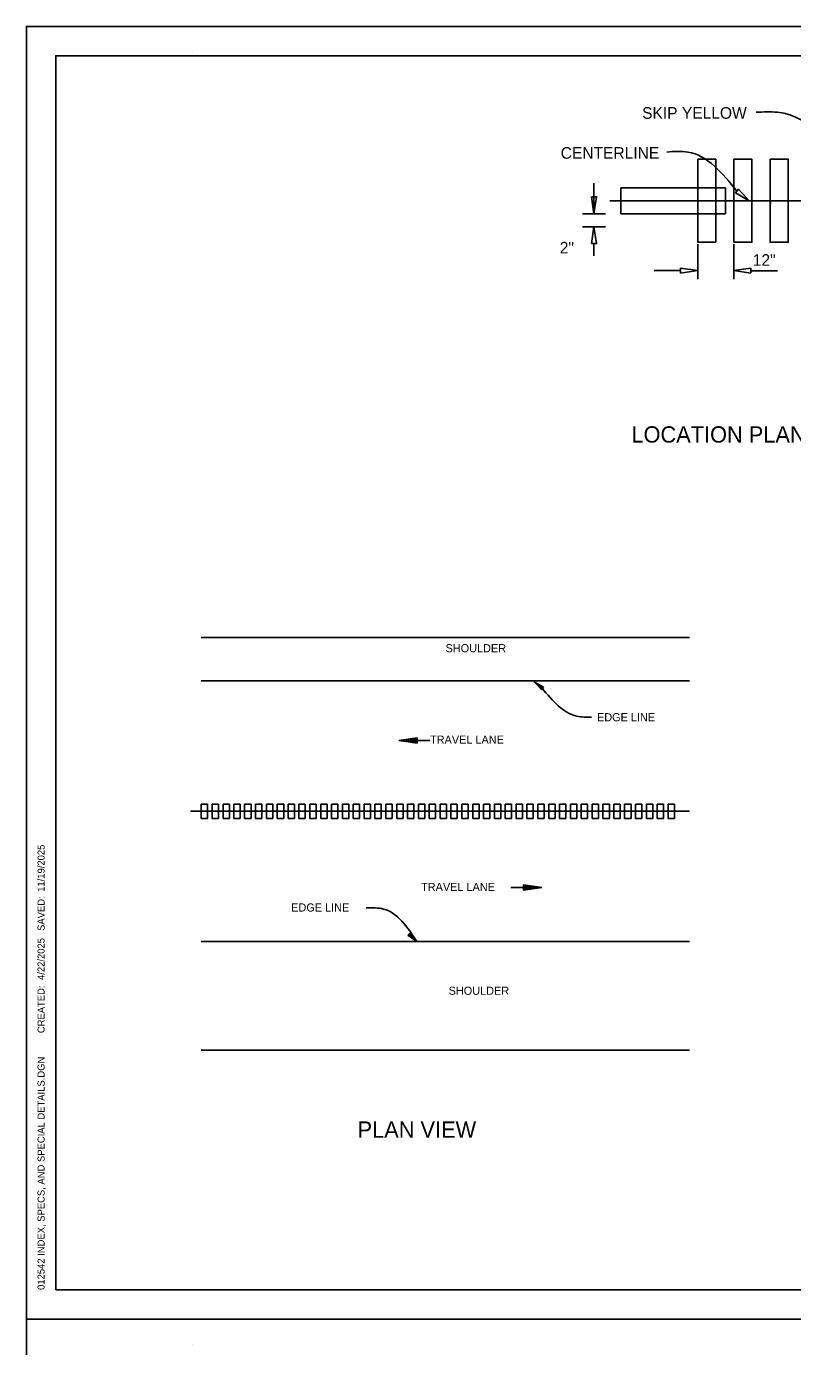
# Model space of a CAD drawing. Extents: x 1371343 to 1376243, y 378740 to 382184.
# Drawn here: x 1371343 to 1371995, y 380917 to 382040 of the extents above; entities that cross this region are included whole.
import ezdxf

# ---------------------------------------------------------------- set-up
doc = ezdxf.new("R2010")
doc.units = 0
for name, color, linetype in [('Default', 7, 'Continuous'), ('SHET_Border-Lines', 7, 'Continuous'), ('SHET_Border-Text', 7, 'Continuous')]:
    doc.layers.add(name, color=color, linetype=linetype)

msp = doc.modelspace()

# ---------------------------------------------------------------- linework, layer by layer
at = {"layer": 'Default'}
for p, q in [((1371826, 381881.1), (1371826, 381907.2)), ((1371849, 381903.2), (1371849, 381881.1)), ((1371849, 381903.2), (1371937.9, 381903.2)), ((1371937.9, 381903.2), (1371937.9, 381881.1)), ((1371839.4, 381892.1), (1372448.3, 381892.1)), ((1371976.3, 381892.1), (1371976.3, 381889.3)), ((1371816.2, 381881.1), (1371835.9, 381881.1)), ((1371849, 381881.1), (1371937.9, 381881.1)), ((1371816.2, 381870.1), (1371835.9, 381870.1)), ((1371826, 381845.4), (1371826, 381855.7)), ((1371914.3, 381825.5), (1371914.3, 381855.1)), ((1371945.1, 381825.4), (1371945.1, 381855.2)), ((1371899.8, 381832.7), (1371877.2, 381832.7)), ((1371982.2, 381832.6), (1371959.5, 381832.6)), ((1371491.8, 381520.5), (1371907.4, 381520.5)), ((1371491.8, 381483.6), (1371698.6, 381483.6)), ((1371907.4, 381483.6), (1371698.6, 381483.6)), ((1371781.5, 381476), (1371775.1, 381482.9)), ((1371783.2, 381478.2), (1371775.1, 381482.9)), ((1371781.6, 381476.2), (1371776.3, 381481.9)), ((1371783.1, 381478), (1371776.3, 381481.9)), ((1371782.9, 381477.8), (1371777.6, 381480.9)), ((1371781.8, 381476.4), (1371777.6, 381480.9)), ((1371781.9, 381476.6), (1371778.8, 381480)), ((1371782.8, 381477.6), (1371778.8, 381480)), ((1371782.6, 381477.4), (1371780, 381479)), ((1371782.1, 381476.7), (1371780, 381479)), ((1371782.5, 381477.3), (1371781.2, 381478)), ((1371782.2, 381476.9), (1371781.2, 381478)), ((1371781.5, 381476), (1371783.2, 381478.2)), ((1371675.5, 381435.2), (1371659.9, 381432.9)), ((1371686.4, 381432.9), (1371659.9, 381432.9)), ((1371675.5, 381430.6), (1371659.9, 381432.9)), ((1371675.5, 381434.8), (1371662.5, 381432.9)), ((1371675.5, 381431), (1371662.5, 381432.9)), ((1371675.5, 381434.5), (1371665.2, 381432.9)), ((1371675.5, 381431.4), (1371665.2, 381432.9)), ((1371675.5, 381434.1), (1371667.7, 381432.9)), ((1371675.5, 381431.7), (1371667.7, 381432.9)), ((1371675.5, 381433.6), (1371670.4, 381432.9)), ((1371675.5, 381432.1), (1371670.4, 381432.9)), ((1371675.5, 381433.3), (1371673, 381432.9)), ((1371675.5, 381432.5), (1371673, 381432.9)), ((1371675.5, 381435.2), (1371675.5, 381430.6)), ((1371497.2, 381378.8), (1371491.8, 381378.8)), ((1371491.8, 381378.8), (1371491.8, 381366.6)), ((1371497.2, 381378.8), (1371497.2, 381366.6)), ((1371506.4, 381378.8), (1371501, 381378.8)), ((1371501, 381378.8), (1371501, 381366.6)), ((1371506.4, 381378.8), (1371506.4, 381366.6)), ((1371515.7, 381378.8), (1371510.3, 381378.8)), ((1371510.3, 381378.8), (1371510.3, 381366.6)), ((1371515.7, 381378.8), (1371515.7, 381366.6)), ((1371524.9, 381378.8), (1371519.5, 381378.8)), ((1371519.5, 381378.8), (1371519.5, 381366.6)), ((1371524.9, 381378.8), (1371524.9, 381366.6)), ((1371534.1, 381378.8), (1371528.7, 381378.8)), ((1371528.7, 381378.8), (1371528.7, 381366.6)), ((1371534.1, 381378.8), (1371534.1, 381366.6)), ((1371543.4, 381378.8), (1371538, 381378.8)), ((1371538, 381378.8), (1371538, 381366.6)), ((1371543.4, 381378.8), (1371543.4, 381366.6)), ((1371552.6, 381378.8), (1371547.2, 381378.8)), ((1371547.2, 381378.8), (1371547.2, 381366.6)), ((1371552.6, 381378.8), (1371552.6, 381366.6)), ((1371561.9, 381378.8), (1371556.5, 381378.8)), ((1371556.5, 381378.8), (1371556.5, 381366.6)), ((1371561.9, 381378.8), (1371561.9, 381366.6)), ((1371571.1, 381378.8), (1371565.7, 381378.8)), ((1371565.7, 381378.8), (1371565.7, 381366.6)), ((1371571.1, 381378.8), (1371571.1, 381366.6)), ((1371580.3, 381378.8), (1371574.9, 381378.8)), ((1371574.9, 381378.8), (1371574.9, 381366.6)), ((1371580.3, 381378.8), (1371580.3, 381366.6)), ((1371589.6, 381378.8), (1371584.2, 381378.8)), ((1371584.2, 381378.8), (1371584.2, 381366.6)), ((1371589.6, 381378.8), (1371589.6, 381366.6)), ((1371598.8, 381378.8), (1371593.4, 381378.8)), ((1371593.4, 381378.8), (1371593.4, 381366.6)), ((1371598.8, 381378.8), (1371598.8, 381366.6)), ((1371608.1, 381378.8), (1371602.7, 381378.8)), ((1371602.7, 381378.8), (1371602.7, 381366.6)), ((1371608.1, 381378.8), (1371608.1, 381366.6)), ((1371617.3, 381378.8), (1371611.9, 381378.8)), ((1371611.9, 381378.8), (1371611.9, 381366.6)), ((1371617.3, 381378.8), (1371617.3, 381366.6)), ((1371626.5, 381378.8), (1371621.1, 381378.8)), ((1371621.1, 381378.8), (1371621.1, 381366.6)), ((1371626.5, 381378.8), (1371626.5, 381366.6)), ((1371635.8, 381378.8), (1371630.4, 381378.8)), ((1371630.4, 381378.8), (1371630.4, 381366.6)), ((1371635.8, 381378.8), (1371635.8, 381366.6)), ((1371645, 381378.8), (1371639.6, 381378.8)), ((1371639.6, 381378.8), (1371639.6, 381366.6)), ((1371645, 381378.8), (1371645, 381366.6)), ((1371654.3, 381378.8), (1371648.9, 381378.8)), ((1371648.9, 381378.8), (1371648.9, 381366.6)), ((1371654.3, 381378.8), (1371654.3, 381366.6)), ((1371663.5, 381378.8), (1371658.1, 381378.8)), ((1371658.1, 381378.8), (1371658.1, 381366.6)), ((1371663.5, 381378.8), (1371663.5, 381366.6)), ((1371672.7, 381378.8), (1371667.3, 381378.8)), ((1371667.3, 381378.8), (1371667.3, 381366.6)), ((1371672.7, 381378.8), (1371672.7, 381366.6)), ((1371682, 381378.8), (1371676.6, 381378.8)), ((1371676.6, 381378.8), (1371676.6, 381366.6)), ((1371682, 381378.8), (1371682, 381366.6)), ((1371691.2, 381378.8), (1371685.8, 381378.8)), ((1371685.8, 381378.8), (1371685.8, 381366.6)), ((1371691.2, 381378.8), (1371691.2, 381366.6)), ((1371700.5, 381378.8), (1371695.1, 381378.8)), ((1371695.1, 381378.8), (1371695.1, 381366.6)), ((1371700.5, 381378.8), (1371700.5, 381366.6)), ((1371709.7, 381378.8), (1371704.3, 381378.8)), ((1371704.3, 381378.8), (1371704.3, 381366.6)), ((1371709.7, 381378.8), (1371709.7, 381366.6)), ((1371719, 381378.8), (1371713.5, 381378.8)), ((1371713.5, 381378.8), (1371713.5, 381366.6)), ((1371719, 381378.8), (1371719, 381366.6)), ((1371728.2, 381378.8), (1371722.8, 381378.8)), ((1371722.8, 381378.8), (1371722.8, 381366.6)), ((1371728.2, 381378.8), (1371728.2, 381366.6)), ((1371737.4, 381378.8), (1371732, 381378.8)), ((1371732, 381378.8), (1371732, 381366.6)), ((1371737.4, 381378.8), (1371737.4, 381366.6)), ((1371746.7, 381378.8), (1371741.3, 381378.8)), ((1371741.3, 381378.8), (1371741.3, 381366.6)), ((1371746.7, 381378.8), (1371746.7, 381366.6)), ((1371755.9, 381378.8), (1371750.5, 381378.8)), ((1371750.5, 381378.8), (1371750.5, 381366.6)), ((1371755.9, 381378.8), (1371755.9, 381366.6)), ((1371765.2, 381378.8), (1371759.7, 381378.8)), ((1371759.7, 381378.8), (1371759.7, 381366.6)), ((1371765.2, 381378.8), (1371765.2, 381366.6)), ((1371774.4, 381378.8), (1371769, 381378.8)), ((1371769, 381378.8), (1371769, 381366.6)), ((1371774.4, 381378.8), (1371774.4, 381366.6)), ((1371783.6, 381378.8), (1371778.2, 381378.8)), ((1371778.2, 381378.8), (1371778.2, 381366.6)), ((1371783.6, 381378.8), (1371783.6, 381366.6)), ((1371792.9, 381378.8), (1371787.5, 381378.8)), ((1371787.5, 381378.8), (1371787.5, 381366.6)), ((1371792.9, 381378.8), (1371792.9, 381366.6)), ((1371802.1, 381378.8), (1371796.7, 381378.8)), ((1371796.7, 381378.8), (1371796.7, 381366.6)), ((1371802.1, 381378.8), (1371802.1, 381366.6)), ((1371811.4, 381378.8), (1371805.9, 381378.8)), ((1371805.9, 381378.8), (1371805.9, 381366.6)), ((1371811.4, 381378.8), (1371811.4, 381366.6)), ((1371820.6, 381378.8), (1371815.2, 381378.8)), ((1371815.2, 381378.8), (1371815.2, 381366.6)), ((1371820.6, 381378.8), (1371820.6, 381366.6)), ((1371829.8, 381378.8), (1371824.4, 381378.8)), ((1371824.4, 381378.8), (1371824.4, 381366.6)), ((1371829.8, 381378.8), (1371829.8, 381366.6)), ((1371839.1, 381378.8), (1371833.7, 381378.8)), ((1371833.7, 381378.8), (1371833.7, 381366.6)), ((1371839.1, 381378.8), (1371839.1, 381366.6)), ((1371848.3, 381378.8), (1371842.9, 381378.8)), ((1371842.9, 381378.8), (1371842.9, 381366.6)), ((1371848.3, 381378.8), (1371848.3, 381366.6)), ((1371857.6, 381378.8), (1371852.1, 381378.8)), ((1371852.1, 381378.8), (1371852.1, 381366.6)), ((1371857.6, 381378.8), (1371857.6, 381366.6)), ((1371866.8, 381378.8), (1371861.4, 381378.8)), ((1371861.4, 381378.8), (1371861.4, 381366.6)), ((1371866.8, 381378.8), (1371866.8, 381366.6)), ((1371876, 381378.8), (1371870.6, 381378.8)), ((1371870.6, 381378.8), (1371870.6, 381366.6)), ((1371876, 381378.8), (1371876, 381366.6)), ((1371885.3, 381378.8), (1371879.9, 381378.8)), ((1371879.9, 381378.8), (1371879.9, 381366.6)), ((1371885.3, 381378.8), (1371885.3, 381366.6)), ((1371894.5, 381378.8), (1371889.1, 381378.8)), ((1371889.1, 381378.8), (1371889.1, 381366.6)), ((1371894.5, 381378.8), (1371894.5, 381366.6)), ((1371482.6, 381372.7), (1371907.4, 381372.7)), ((1371491.8, 381366.6), (1371497.2, 381366.6)), ((1371501, 381366.6), (1371506.4, 381366.6)), ((1371510.3, 381366.6), (1371515.7, 381366.6)), ((1371519.5, 381366.6), (1371524.9, 381366.6)), ((1371528.7, 381366.6), (1371534.1, 381366.6)), ((1371538, 381366.6), (1371543.4, 381366.6)), ((1371547.2, 381366.6), (1371552.6, 381366.6)), ((1371556.5, 381366.6), (1371561.9, 381366.6)), ((1371565.7, 381366.6), (1371571.1, 381366.6)), ((1371574.9, 381366.6), (1371580.3, 381366.6)), ((1371584.2, 381366.6), (1371589.6, 381366.6)), ((1371593.4, 381366.6), (1371598.8, 381366.6)), ((1371602.7, 381366.6), (1371608.1, 381366.6)), ((1371611.9, 381366.6), (1371617.3, 381366.6)), ((1371621.1, 381366.6), (1371626.5, 381366.6)), ((1371630.4, 381366.6), (1371635.8, 381366.6)), ((1371639.6, 381366.6), (1371645, 381366.6)), ((1371648.9, 381366.6), (1371654.3, 381366.6)), ((1371658.1, 381366.6), (1371663.5, 381366.6)), ((1371667.3, 381366.6), (1371672.7, 381366.6)), ((1371676.6, 381366.6), (1371682, 381366.6)), ((1371685.8, 381366.6), (1371691.2, 381366.6)), ((1371695.1, 381366.6), (1371700.5, 381366.6)), ((1371704.3, 381366.6), (1371709.7, 381366.6)), ((1371713.5, 381366.6), (1371719, 381366.6)), ((1371722.8, 381366.6), (1371728.2, 381366.6)), ((1371732, 381366.6), (1371737.4, 381366.6)), ((1371741.3, 381366.6), (1371746.7, 381366.6)), ((1371750.5, 381366.6), (1371755.9, 381366.6)), ((1371759.7, 381366.6), (1371765.2, 381366.6)), ((1371769, 381366.6), (1371774.4, 381366.6)), ((1371778.2, 381366.6), (1371783.6, 381366.6)), ((1371787.5, 381366.6), (1371792.9, 381366.6)), ((1371796.7, 381366.6), (1371802.1, 381366.6)), ((1371805.9, 381366.6), (1371811.4, 381366.6)), ((1371815.2, 381366.6), (1371820.6, 381366.6)), ((1371824.4, 381366.6), (1371829.8, 381366.6)), ((1371833.7, 381366.6), (1371839.1, 381366.6)), ((1371842.9, 381366.6), (1371848.3, 381366.6)), ((1371852.1, 381366.6), (1371857.6, 381366.6)), ((1371861.4, 381366.6), (1371866.8, 381366.6)), ((1371870.6, 381366.6), (1371876, 381366.6)), ((1371879.9, 381366.6), (1371885.3, 381366.6)), ((1371889.1, 381366.6), (1371894.5, 381366.6)), ((1371755.2, 381307.8), (1371781.6, 381307.8)), ((1371766.1, 381310.1), (1371781.6, 381307.8)), ((1371766.1, 381305.5), (1371766.1, 381310.1)), ((1371766.1, 381309.7), (1371779, 381307.8)), ((1371766.1, 381309.3), (1371776.4, 381307.8)), ((1371766.1, 381308.9), (1371773.8, 381307.8)), ((1371766.1, 381308.6), (1371771.1, 381307.8)), ((1371766.1, 381308.2), (1371768.5, 381307.8)), ((1371766.1, 381305.5), (1371781.6, 381307.8)), ((1371766.1, 381307.1), (1371771.1, 381307.8)), ((1371766.1, 381306.2), (1371776.4, 381307.8)), ((1371766.1, 381305.8), (1371779, 381307.8)), ((1371766.1, 381306.6), (1371773.8, 381307.8)), ((1371766.1, 381307.4), (1371768.5, 381307.8)), ((1371669.7, 381269.3), (1371667.7, 381267.3)), ((1371667.7, 381267.3), (1371675.3, 381261.9)), ((1371667.9, 381267.5), (1371674.2, 381263)), ((1371668.1, 381267.7), (1371673.1, 381264.1)), ((1371668.2, 381267.8), (1371672, 381265.1)), ((1371668.4, 381268), (1371670.9, 381266.2)), ((1371668.5, 381268.2), (1371669.7, 381267.3)), ((1371668.8, 381268.5), (1371669.7, 381267.3)), ((1371669, 381268.6), (1371670.9, 381266.2)), ((1371669.2, 381268.8), (1371672, 381265.1)), ((1371669.3, 381269), (1371673.1, 381264.1)), ((1371669.5, 381269.1), (1371674.2, 381263)), ((1371669.7, 381269.3), (1371675.3, 381261.9)), ((1371491.8, 381261.8), (1371698.6, 381261.8)), ((1371907.4, 381261.8), (1371698.6, 381261.8)), ((1371805.9, 381261.8), (1371907.4, 381261.8)), ((1371491.8, 381169.4), (1371907.4, 381169.4))]:
    msp.add_line(p, q, dxfattribs=at)
for points in [[(1371342.9, 382040.5), (1371342.9, 380940.5), (1373042.9, 380940.5), (1373042.9, 382040.5)], [(1371914.3, 381927.4), (1371914.3, 381856.9), (1371929.7, 381856.9), (1371929.7, 381927.4)], [(1371945.1, 381927.4), (1371945.1, 381856.9), (1371960.5, 381856.9), (1371960.5, 381927.4)], [(1371975.9, 381927.4), (1371975.9, 381856.9), (1371991.4, 381856.9), (1371991.4, 381927.4)], [(1371823.8, 381895.6), (1371828.2, 381895.6), (1371826, 381881.1)], [(1371946.4, 381898.8), (1371948.9, 381902), (1371958, 381892.1)], [(1371823.8, 381855.7), (1371828.2, 381855.7), (1371826, 381870.1)], [(1371899.8, 381830.5), (1371899.8, 381834.9), (1371914.3, 381832.7)], [(1371959.5, 381830.5), (1371959.5, 381834.8), (1371945.1, 381832.7)], [(1371342.9, 380940.5), (1371342.9, 379840.5), (1373042.9, 379840.5), (1373042.9, 380940.5)]]:
    msp.add_lwpolyline(points, close=True, dxfattribs=at)
for points in [[(1371964, 381967.4), (1371982.2, 381967.4), (1372052.5, 381911.4)], [(1371888.1, 381933.6), (1371906, 381933.6), (1371947.7, 381900.4)], [(1371824, 381452.8), (1371811.4, 381453.7), (1371782, 381477.2)], [(1371632.1, 381290.5), (1371646.9, 381289.5), (1371675.3, 381261.9)]]:
    msp.add_spline(points, degree=3, dxfattribs=at)
at = {"layer": 'SHET_Border-Lines'}
for p, q in [((1371484, 382019.1), (1371484, 382019.1)), ((1371484, 382019.1), (1371484, 382019.1)), ((1371484, 380919.1), (1371484, 380919.1)), ((1371484, 380919.1), (1371484, 380919.1))]:
    msp.add_line(p, q, dxfattribs=at)
for points in [[(1371342.9, 380940.5), (1373042.9, 380940.5), (1373042.9, 382040.5), (1371342.9, 382040.5)], [(1371367.9, 380965.5), (1373017.9, 380965.5), (1373017.9, 382015.5), (1371367.9, 382015.5)], [(1371342.9, 379840.5), (1373042.9, 379840.5), (1373042.9, 380940.5), (1371342.9, 380940.5)]]:
    msp.add_lwpolyline(points, close=True, dxfattribs=at)

# ---------------------------------------------------------------- texts
at = {"layer": 'Default'}
for s, height, p in [('SKIP YELLOW', 9.9, (1371867, 381961.9)), ('CENTERLINE', 9.9, (1371797.7, 381927.9)), ('2"', 9.9, (1371796.9, 381847.3)), ('12"', 9.9, (1371961.2, 381836.8)), ('LOCATION PLAN OF CENTERLINE RUMBLE STRIPES', 13.86, (1371857.9, 381686.4)), ('SHOULDER', 6.93, (1371699.7, 381508)), ('EDGE LINE', 6.93, (1371828.6, 381449.3)), ('TRAVEL LANE', 6.93, (1371686.5, 381430.2)), ('TRAVEL LANE', 6.93, (1371678.9, 381304.9)), ('EDGE LINE', 6.93, (1371568.3, 381287.4)), ('SHOULDER', 6.93, (1371702.3, 381216.6)), ('PLAN VIEW ', 13.86, (1371624.8, 381095))]:
    msp.add_text(s, height=height, dxfattribs=at).set_placement(p)
at = {"layer": 'SHET_Border-Text'}
for s, p in [('11/19/2025', (1371358.4, 381304.2)), ('  SAVED: ', (1371358.4, 381266.5)), ('4/22/2025', (1371358.4, 381229.2)), ('     CREATED: ', (1371358.4, 381172.8)), ('012542 INDEX, SPECS, AND SPECIAL DETAILS.DGN', (1371358.4, 380965.5))]:
    msp.add_text(s, height=6, rotation=90, dxfattribs=at).set_placement(p)

doc.saveas('drawing.dxf')
